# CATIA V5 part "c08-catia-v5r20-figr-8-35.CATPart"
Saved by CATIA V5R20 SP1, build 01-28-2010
Part number: Part1
Bounding box of the stored display mesh (mm): x -75 to 75, y -75 to 75, z 0 to 20
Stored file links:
  D:\v5_r20\psrt_files_downloaded\c08-catia-v5r20-prt\c08-catia-v5r20-figr-8-35.CATPart
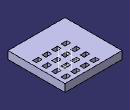
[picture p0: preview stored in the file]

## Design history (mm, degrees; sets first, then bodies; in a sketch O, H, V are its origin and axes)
Body1 (main body)
  Sketch1 on xy-plane, origin (0, 0, 0), H (1, 0, 0), V (0, 1, 0)
    line L1 (-75, 75) -> (75, 75)
    line L2 (75, 75) -> (75, -75)
    line L3 (75, -75) -> (-75, -75)
    line L4 (-75, -75) -> (-75, 75)
    axis line L5 (75, -75) -> (-75, 75)
    length L3 = 150
    length L2 = 150
    horizontal: L1 H, L3 H
    vertical: L2 V, L4 V
    midpoint: O L5
  Pad1: profile Sketch1, direction (0, 0, 1), length 20
  Sketch2 on face of Pad1, origin (0, 0, 20), H (1, 0, 0), V (0, 1, 0)
    line L1 (25, 40) -> (40, 40)
    line L2 (40, 40) -> (40, 30)
    line L3 (40, 30) -> (25, 30)
    line L4 (25, 30) -> (25, 40)
    reference projected line E1 (75, -75) -> (75, 75) from edge [face of Pad1 | face of Pad1]
    reference projected line E2 (75, 75) -> (-75, 75) from edge [face of Pad1 | face of Pad1]
    length L3 = 15
    length L4 = 10
    distance L2 E1 = 35
    distance L1 E2 = 35
    horizontal: L1 H, L3 H
    vertical: L2 V, L4 V
  Pocket1: profile Sketch2, direction (0, 0, -1), through (limit type 3)
  RectPattern1: of Pocket1, direction 1 instances 4, spacing 25, along edge [face of Pad1 | face of Pad1] reversed, direction 2 instances 4, spacing 25, along edge [face of Pad1 | face of Pad1], Nu 2, Nv 2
